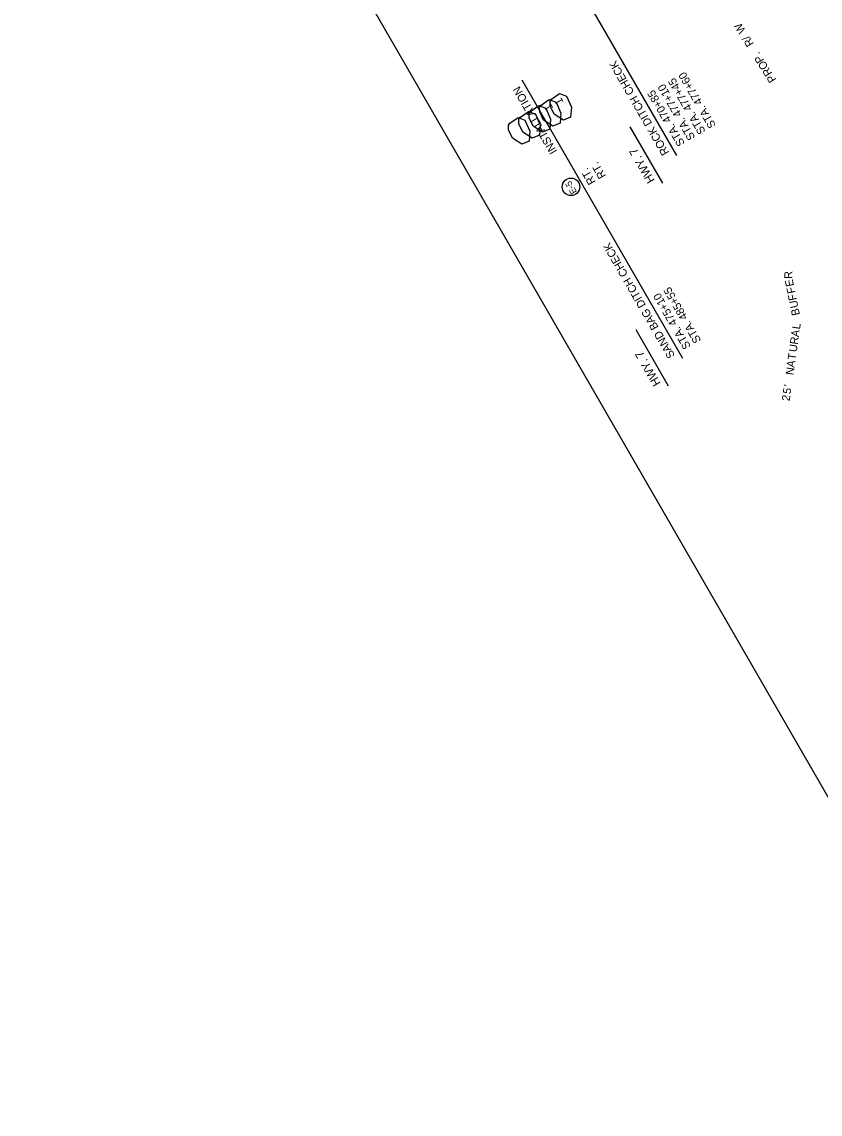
# Model space of a CAD drawing. Extents: x 956270 to 957915, y 1920520 to 1922423.
# Drawn here: x 956270 to 956869, y 1920520 to 1921340 of the extents above; entities that cross this region are included whole.
import ezdxf

# ---------------------------------------------------------------- set-up
doc = ezdxf.new("R2010")
doc.units = 0
for name, color, linetype in [('1', 7, 'Continuous'), ('44', 7, 'Continuous'), ('NO PLOT', 7, 'Continuous'), ('R_Draft', 7, 'Continuous'), ('S_TREE', 7, 'Continuous')]:
    doc.layers.add(name, color=color, linetype=linetype)

msp = doc.modelspace()

# ---------------------------------------------------------------- linework, layer by layer
at = {"layer": '1'}
msp.add_circle((956682.31, 1921215.91), 6.61, dxfattribs=at)
at = {"layer": '44'}
for p, q in [((956761.75, 1921239.33), (956641.25, 1921448.05)), ((956766.19, 1921087.09), (956645.68, 1921295.81)), ((956751.13, 1921218.55), (956726.71, 1921260.85)), ((956755.56, 1921066.31), (956731.14, 1921108.61))]:
    msp.add_line(p, q, dxfattribs=at)
at = {"layer": 'NO PLOT'}
msp.add_lwpolyline([(957012.51, 1920520.44), (956420.48, 1921545.87), (956463.26, 1921570.57), (956365.36, 1921740.14), (956378, 1921747.44), (956270.25, 1921934.07), (956666.17, 1922162.65), (956816.66, 1921901.98), (956749.98, 1921863.48), (956962.48, 1921495.42), (957029.16, 1921533.92), (957172.25, 1921286.08), (957120.9, 1921256.43), (957292.23, 1920959.68), (957343.58, 1920989.33), (957463.85, 1920781.02)], close=True, dxfattribs=at)
msp.add_lwpolyline([(957012.51, 1920520.44), (956420.48, 1921545.87), (956463.26, 1921570.57), (956365.36, 1921740.14), (956378, 1921747.44), (956270.25, 1921934.07), (956666.17, 1922162.65), (956816.66, 1921901.98), (956749.98, 1921863.48), (956962.48, 1921495.42), (957029.16, 1921533.92), (957172.25, 1921286.08), (957120.9, 1921256.43), (957292.23, 1920959.68), (957343.58, 1920989.33), (957463.85, 1920781.02)], close=True, dxfattribs=at)
msp.add_lwpolyline([(957012.51, 1920520.44), (956420.48, 1921545.87), (956463.26, 1921570.57), (956365.36, 1921740.14), (956378, 1921747.44), (956270.25, 1921934.07), (956666.17, 1922162.65), (956816.66, 1921901.98), (956749.98, 1921863.48), (956962.48, 1921495.42), (957029.16, 1921533.92), (957172.25, 1921286.08), (957120.9, 1921256.43), (957292.23, 1920959.68), (957343.58, 1920989.33), (957463.85, 1920781.02)], close=True, dxfattribs=at)
at = {"layer": 'S_TREE'}
for points in [[(956659.19, 1921276.59), (956665.94, 1921281.32), (956671.17, 1921279.46), (956674.82, 1921271.14), (956674.2, 1921263.54), (956668.8, 1921261.29), (956661.79, 1921266.03), (956658.84, 1921272.06), (956658.81, 1921275.76), (956659.78, 1921277.17)], [(956666.98, 1921281.09), (956673.73, 1921285.82), (956678.97, 1921283.96), (956682.61, 1921275.64), (956681.99, 1921268.04), (956676.6, 1921265.79), (956669.59, 1921270.53), (956666.64, 1921276.56), (956666.61, 1921280.26), (956667.57, 1921281.67)], [(956643.6, 1921267.59), (956650.35, 1921272.32), (956655.58, 1921270.46), (956659.23, 1921262.14), (956658.61, 1921254.54), (956653.21, 1921252.29), (956646.2, 1921257.03), (956643.26, 1921263.06), (956643.22, 1921266.76), (956644.19, 1921268.17)], [(956643.6, 1921267.59), (956650.35, 1921272.32), (956655.58, 1921270.46), (956659.23, 1921262.14), (956658.61, 1921254.54), (956653.21, 1921252.29), (956646.2, 1921257.03), (956643.26, 1921263.06), (956643.22, 1921266.76), (956644.19, 1921268.17)], [(956643.6, 1921267.59), (956650.35, 1921272.32), (956655.58, 1921270.46), (956659.23, 1921262.14), (956658.61, 1921254.54), (956653.21, 1921252.29), (956646.2, 1921257.03), (956643.26, 1921263.06), (956643.22, 1921266.76), (956644.19, 1921268.17)], [(956651.39, 1921272.09), (956658.15, 1921276.82), (956663.38, 1921274.96), (956667.03, 1921266.64), (956666.4, 1921259.04), (956661.01, 1921256.79), (956654, 1921261.53), (956651.05, 1921267.56), (956651.02, 1921271.26), (956651.98, 1921272.67)], [(956651.39, 1921272.09), (956658.15, 1921276.82), (956663.38, 1921274.96), (956667.03, 1921266.64), (956666.4, 1921259.04), (956661.01, 1921256.79), (956654, 1921261.53), (956651.05, 1921267.56), (956651.02, 1921271.26), (956651.98, 1921272.67)], [(956651.39, 1921272.09), (956658.15, 1921276.82), (956663.38, 1921274.96), (956667.03, 1921266.64), (956666.4, 1921259.04), (956661.01, 1921256.79), (956654, 1921261.53), (956651.05, 1921267.56), (956651.02, 1921271.26), (956651.98, 1921272.67)], [(956651.39, 1921272.09), (956658.15, 1921276.82), (956663.38, 1921274.96), (956667.03, 1921266.64), (956666.4, 1921259.04), (956661.01, 1921256.79), (956654, 1921261.53), (956651.05, 1921267.56), (956651.02, 1921271.26), (956651.98, 1921272.67)], [(956651.39, 1921272.09), (956658.15, 1921276.82), (956663.38, 1921274.96), (956667.03, 1921266.64), (956666.4, 1921259.04), (956661.01, 1921256.79), (956654, 1921261.53), (956651.05, 1921267.56), (956651.02, 1921271.26), (956651.98, 1921272.67)], [(956635.8, 1921263.09), (956642.56, 1921267.82), (956647.79, 1921265.96), (956651.44, 1921257.64), (956650.81, 1921250.04), (956645.42, 1921247.79), (956638.41, 1921252.53), (956635.46, 1921258.56), (956635.43, 1921262.26), (956636.39, 1921263.67)], [(956635.8, 1921263.09), (956642.56, 1921267.82), (956647.79, 1921265.96), (956651.44, 1921257.64), (956650.81, 1921250.04), (956645.42, 1921247.79), (956638.41, 1921252.53), (956635.46, 1921258.56), (956635.43, 1921262.26), (956636.39, 1921263.67)]]:
    msp.add_lwpolyline(points, dxfattribs=at)

# ---------------------------------------------------------------- texts
at = {"layer": '1'}
msp.add_text('E-5 ', height=4.8, rotation=120, dxfattribs=at).set_placement((956686.87, 1921212.19))
at = {"layer": '44'}
for s, height, p in [('ROCK DITCH CHECK', 6, (956756.1, 1921241.6)), ('STA. 477+45', 6, (956783.53, 1921257.44)), ('STA. 477+60', 6, (956791.33, 1921261.94)), ('INSTALLATION', 6, (956672.11, 1921242.52)), ('STA. 470+85', 6, (956767.94, 1921248.44)), ('STA. 477+10', 6, (956775.74, 1921252.94)), ('1', 6, (956676.99, 1921279.46)), ('1', 6, (956669.19, 1921274.96)), ('HWY. 7', 6.25, (956745.43, 1921220.85)), ('RT.', 6, (956708.76, 1921224.09)), ('RT.', 6, (956700.97, 1921219.59)), ('SAND BAG DITCH CHECK', 6, (956760.54, 1921089.36)), ('STA. 475+10', 6, (956772.38, 1921096.2)), ('STA. 485+55', 6, (956780.17, 1921100.7)), ('HWY. 7', 6.25, (956749.87, 1921068.61))]:
    msp.add_text(s, height=height, rotation=120, dxfattribs=at).set_placement(p)
at = {"layer": 'R_Draft'}
for s, rotation, p in [('W', 122.05288, (956813.6, 1921333.05)), ('/', 122.05288, (956816.71, 1921328.09)), ('R', 122.05288, (956819.72, 1921323.28)), ('P', 122.05288, (956827.46, 1921310.91)), ('.', 122.05288, (956824.46, 1921315.71)), ('O', 122.05288, (956830.57, 1921305.94)), ('R', 122.05288, (956833.58, 1921301.14)), ('P', 122.05288, (956836.59, 1921296.33)), ('R', 92.10778, (956848.49, 1921147.03)), ('E', 101.55546, (956849.68, 1921141.77)), ('F', 101.55546, (956850.76, 1921136.49)), ('F', 101.55546, (956851.84, 1921131.22)), ('U', 101.55546, (956852.99, 1921125.57)), ('B', 101.55546, (956854.13, 1921120.02)), ('A', 81.81509, (956853.27, 1921102.99)), ('L', 81.81509, (956854.11, 1921108.79)), ('R', 81.81509, (956852.46, 1921097.38)), ('U', 81.81509, (956851.64, 1921091.68)), ('A', 81.81509, (956849.98, 1921080.08)), ('T', 81.81509, (956850.81, 1921085.88)), ('N', 81.81509, (956849.17, 1921074.47)), ("'", 81.81509, (956847.9, 1921065.63)), ('2', 81.81509, (956846.36, 1921054.97)), ('5', 81.81509, (956847.13, 1921060.3))]:
    msp.add_text(s, height=6, rotation=rotation, dxfattribs=at).set_placement(p)

doc.saveas('drawing.dxf')
